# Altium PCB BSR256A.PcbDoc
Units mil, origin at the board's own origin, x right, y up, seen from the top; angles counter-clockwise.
Board outline 2710.5 x 1796.5 mil, 4 copper layers (Top Layer, Signal Layer 1, Signal Layer 2, Bottom Layer), stack 60.434 mil thick; 42 components, 12 nets, 58 pads, 44 vias.
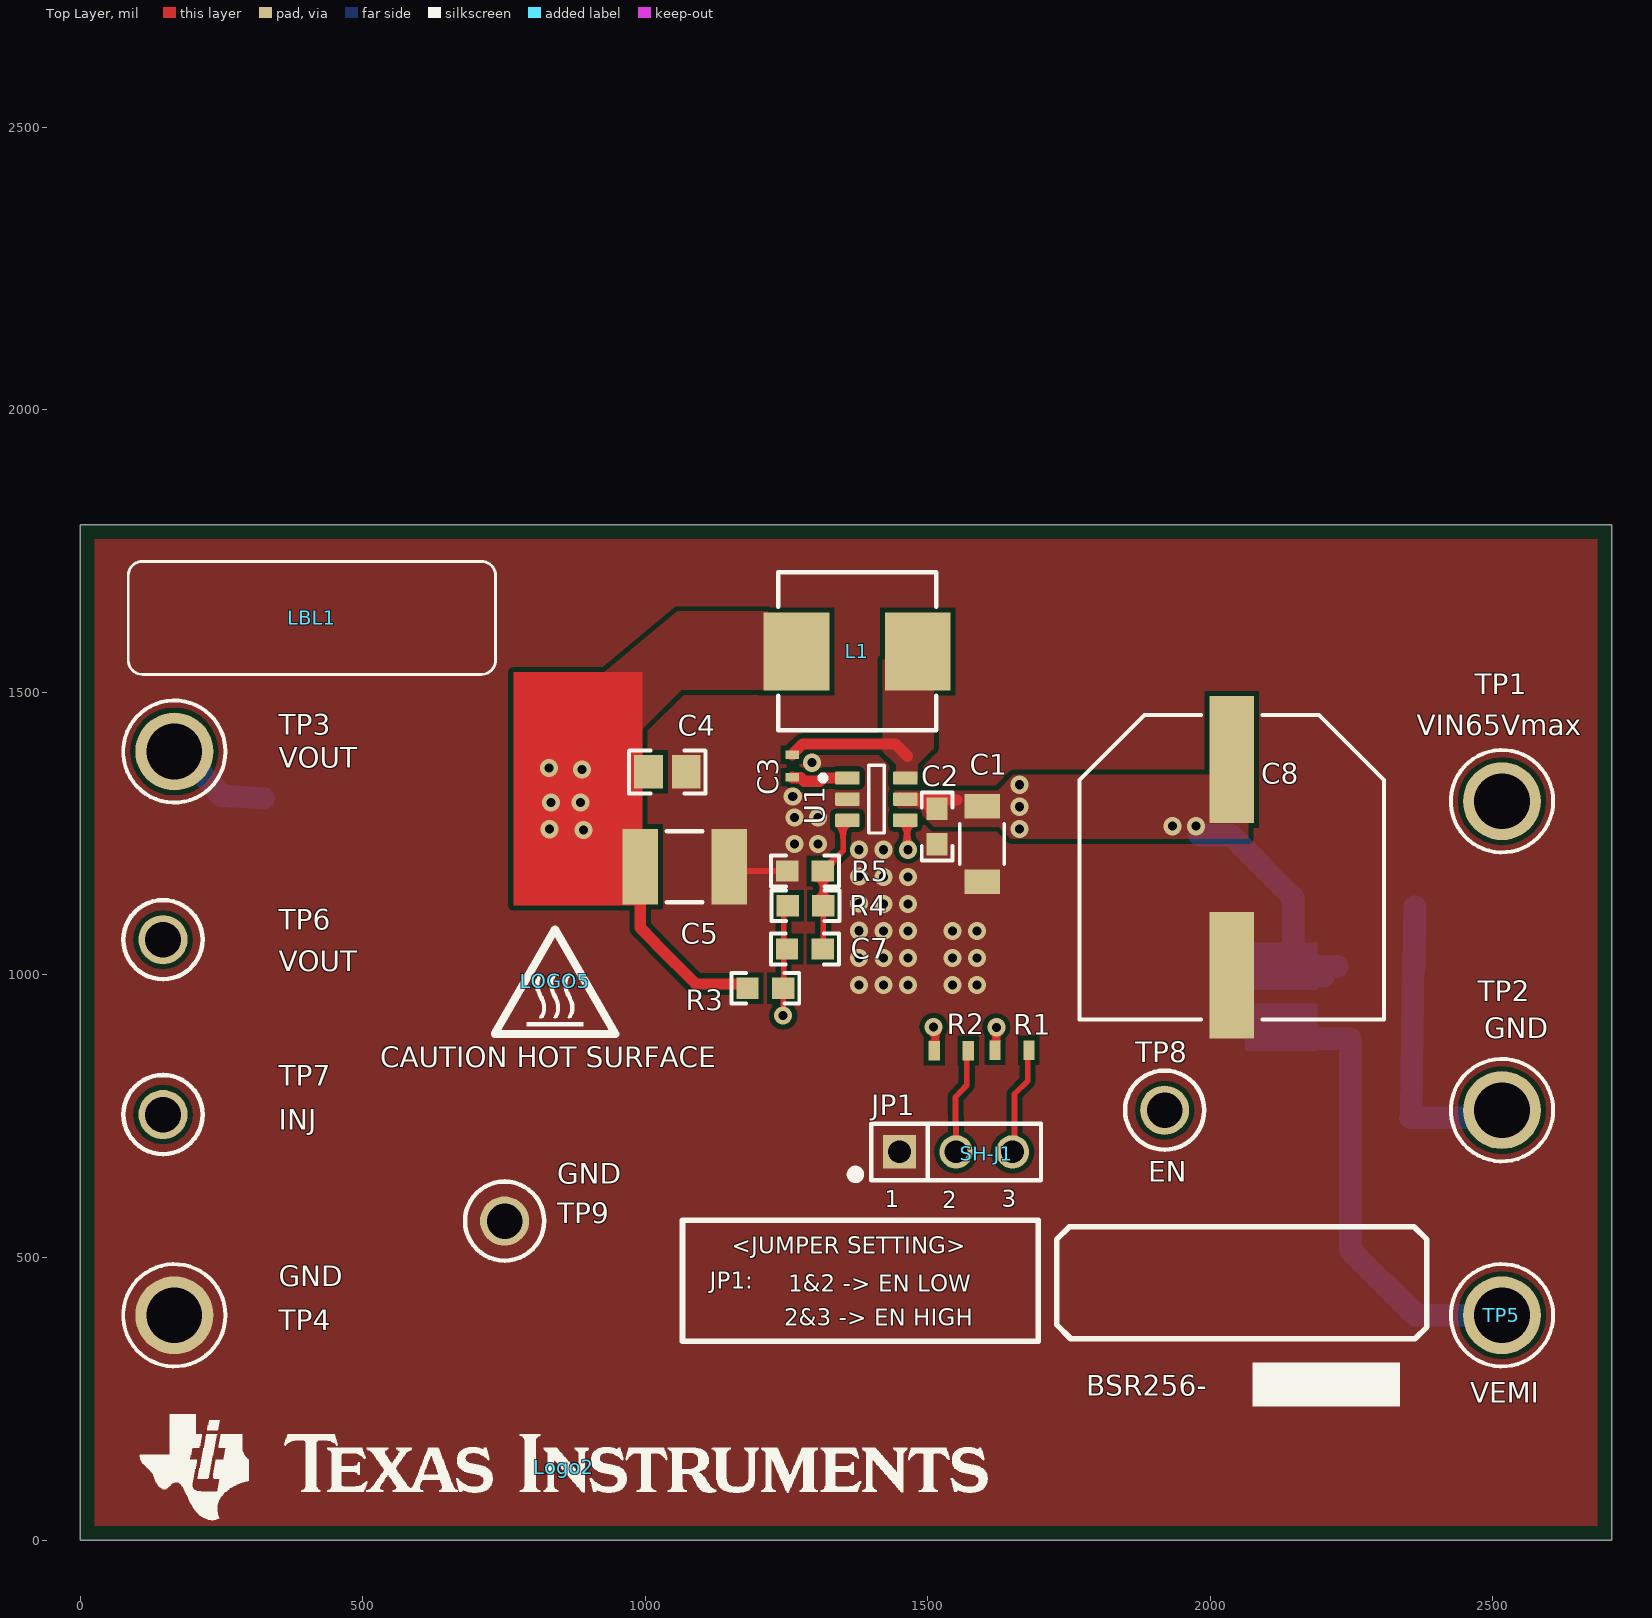
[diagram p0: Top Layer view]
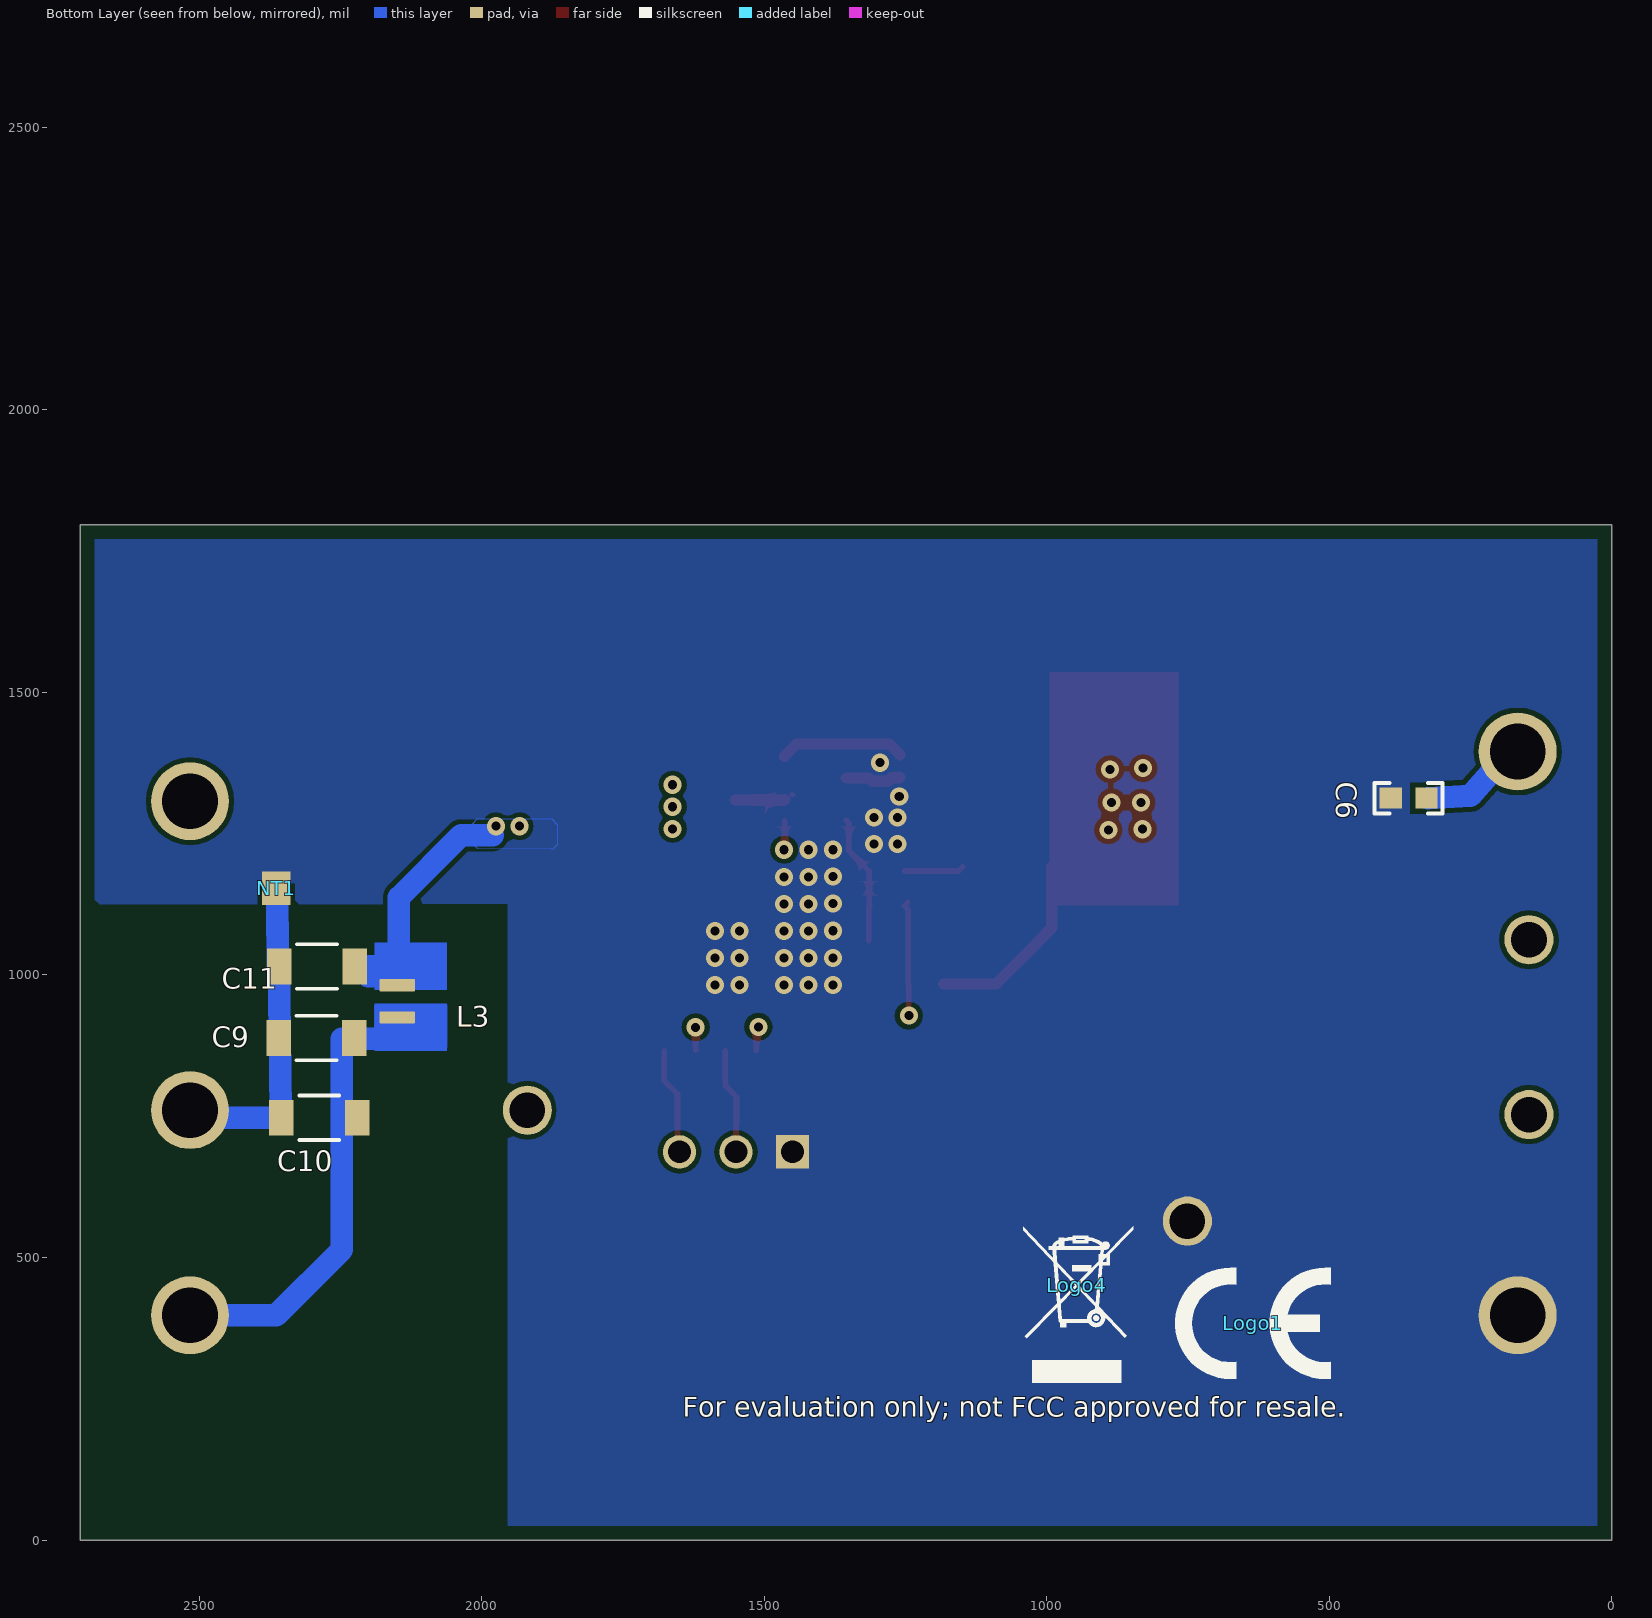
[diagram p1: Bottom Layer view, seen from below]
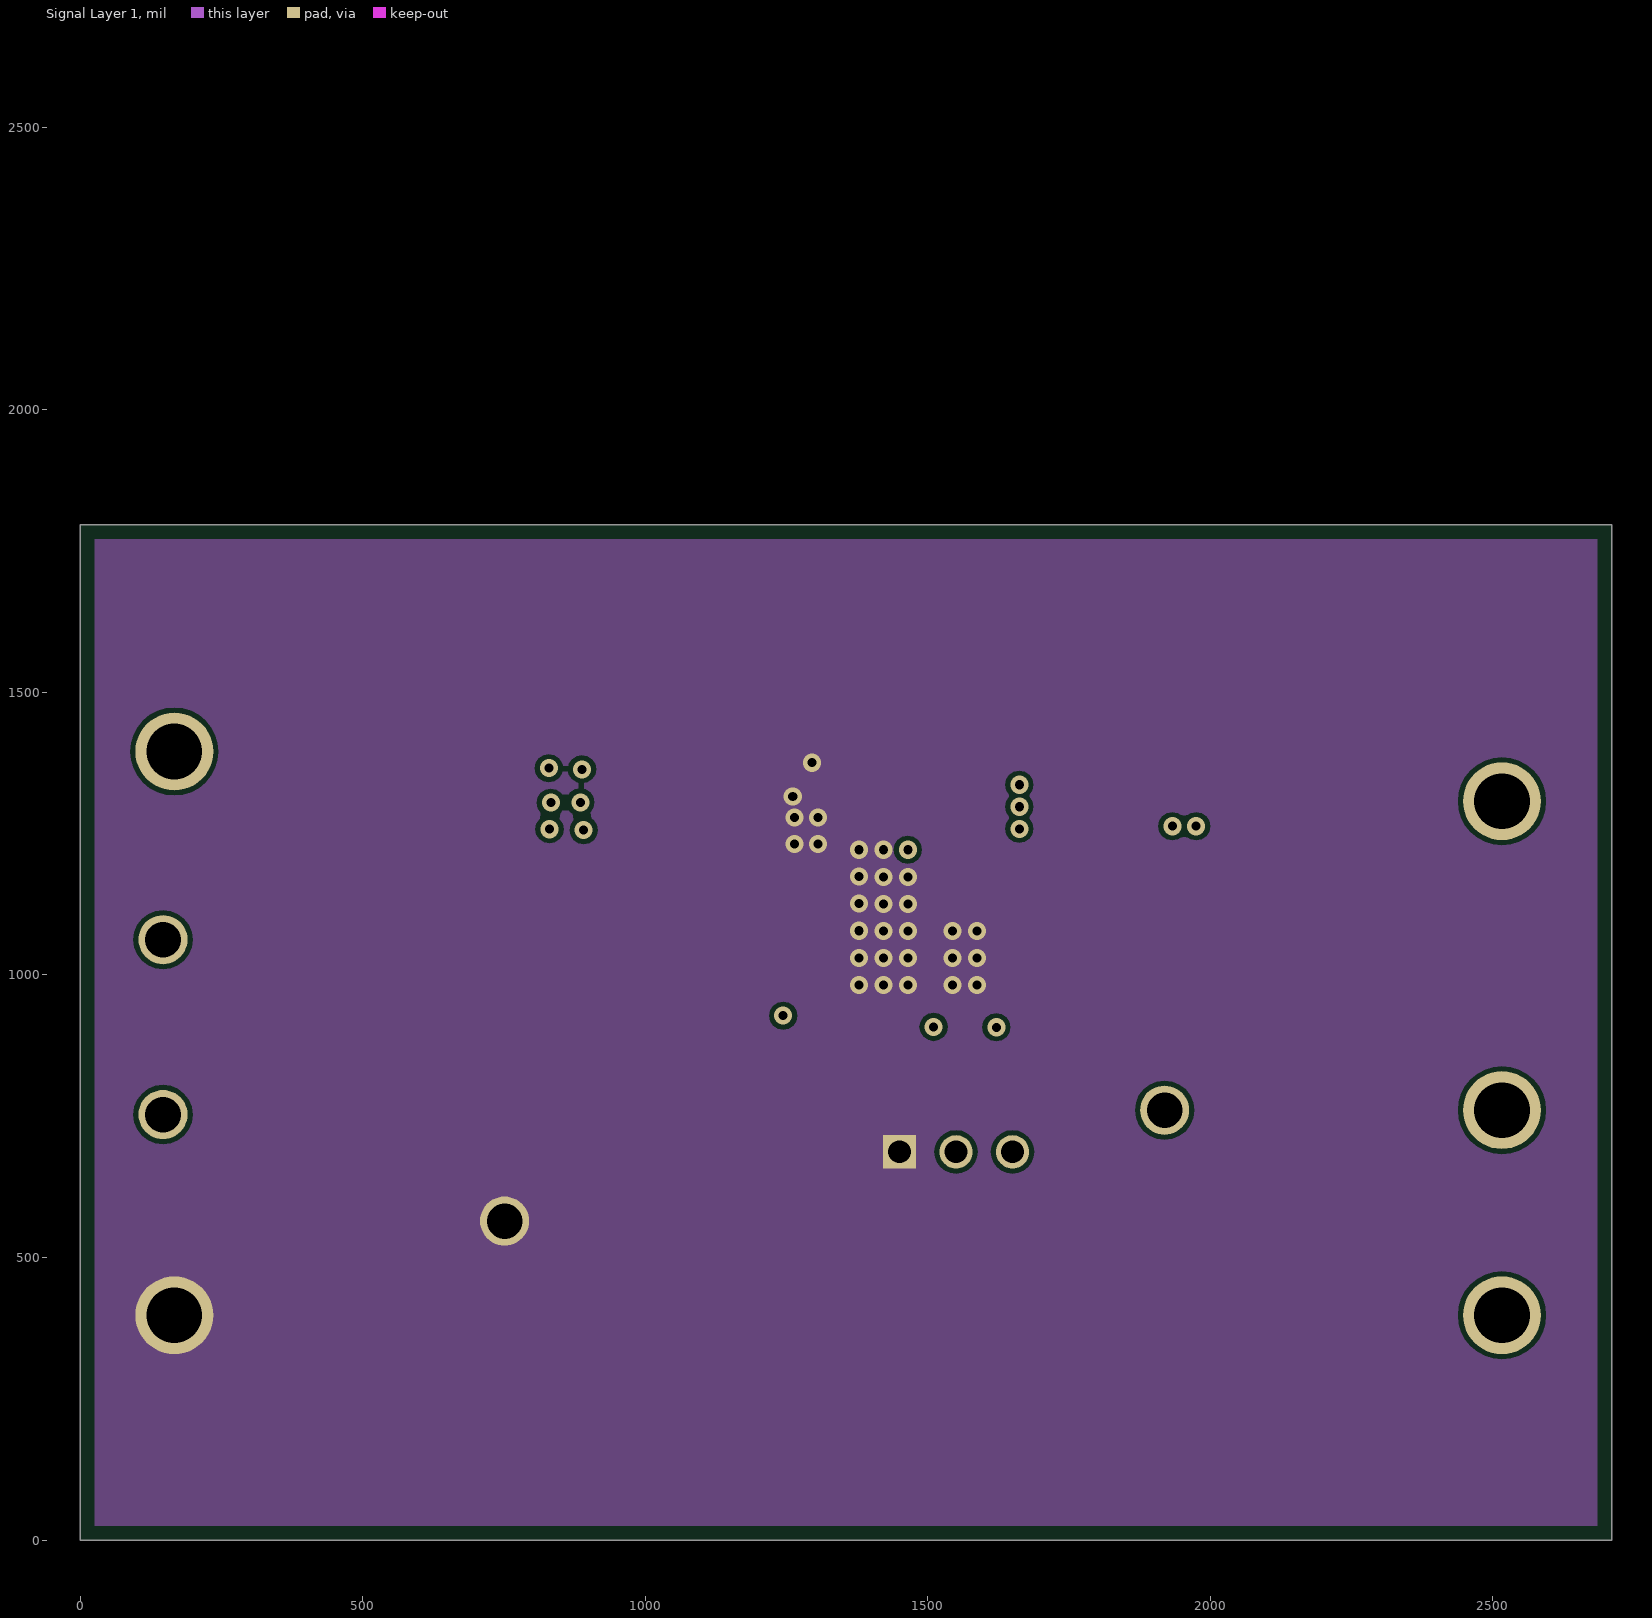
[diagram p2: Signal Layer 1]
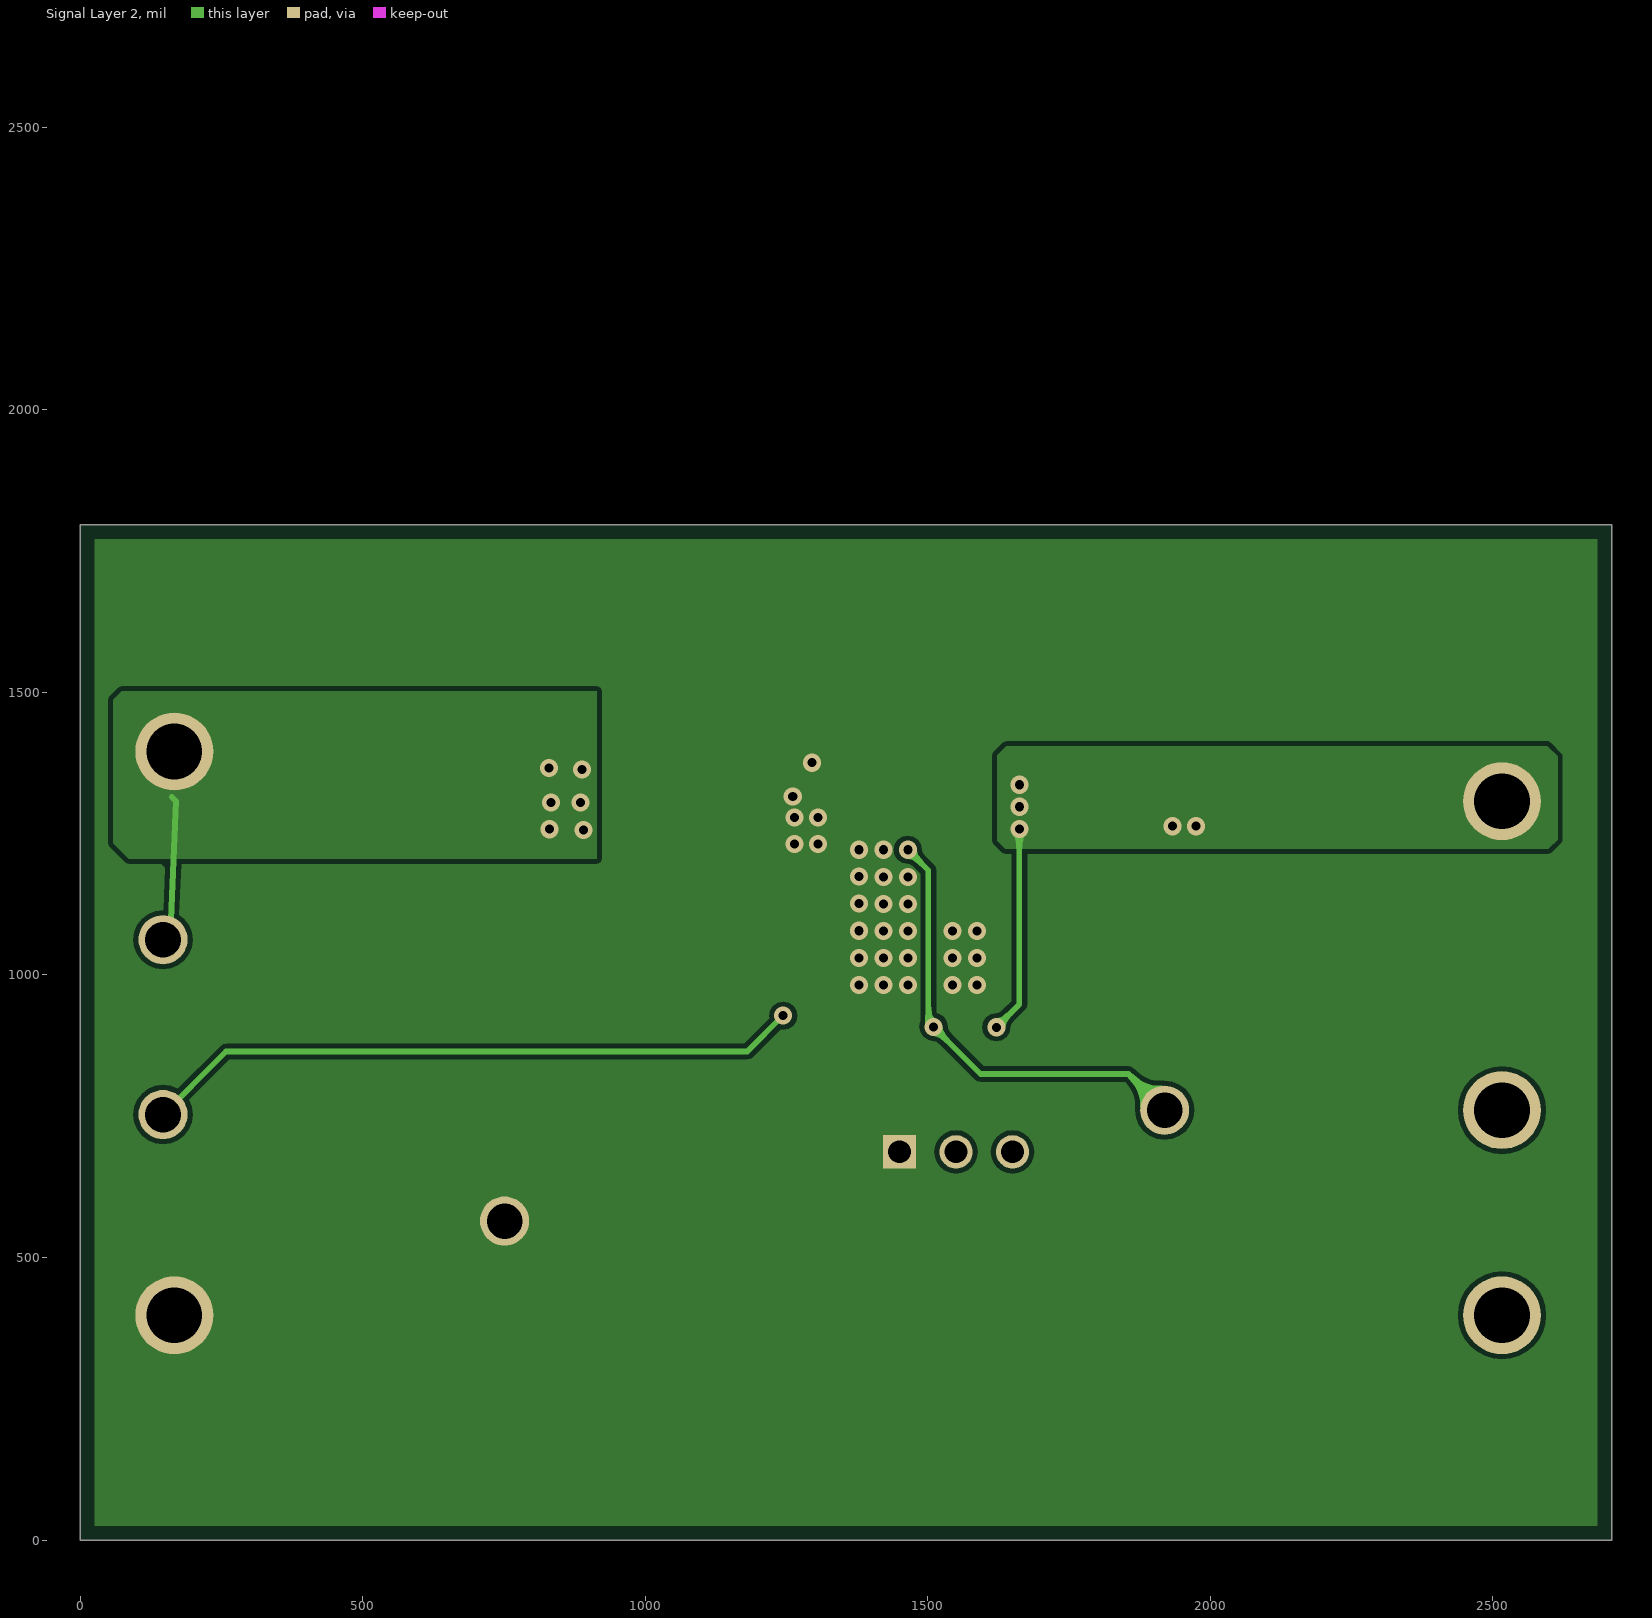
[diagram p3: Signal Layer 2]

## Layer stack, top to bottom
Top Solder: solder mask 0.4, Solder Resist, Dk 3.5
Top Layer: signal copper 2.8
Dielectric1: core 10, FR-4 High Tg, Dk 4.8
Signal Layer 1: signal copper 1.417
Dielectric 2: dielectric 32, FR-4 High Tg, Dk 4.2
Signal Layer 2: signal copper 1.417
Dielectric 3: dielectric 10, FR-4 High Tg, Dk 4.2
Bottom Layer: signal copper 2.8
Bottom Solder: solder mask 0.4, Solder Resist, Dk 3.5

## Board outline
0,0 0,1796.5 2710.5,1796.5 2710.5,0

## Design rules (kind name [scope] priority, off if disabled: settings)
AcuteAngle [All] p1: minimum=4.50000000000000E+0001 checktracksonly=FALSE
AssemblyTestPointUsage [All] p1: valid=2
BoardOutlineClearance BoardOutlineClearance_MountingHoles [OnCopper and InComponentClass('Mounting Holes')] p1: gap=40 ignorepadtopadclearanceinfootprint=FALSE
BoardOutlineClearance BoardOutlineClearance_Poly [OnCopper and IsPoly] p2: gap=25 ignorepadtopadclearanceinfootprint=FALSE
BoardOutlineClearance [OnCopper and Not InComponentClass('Logo') and not InComponentClass('FiducialMark') and not InRegion(1000,500,4000,800) and not InPoly] p3: gap=75 ignorepadtopadclearanceinfootprint=FALSE
Clearance Clearance_Keepouts [((IsTrack Or IsArc) And Not InPoly) And IsFree and IsKeepOut vs ((IsTrack Or IsArc) And Not InPoly) And IsFree and IsKeepOut] p1: gap=7 ignorepadtopadclearanceinfootprint=FALSE
Clearance Clearance_Poly [InPolygon] p2: gap=8.5 ignorepadtopadclearanceinfootprint=FALSE except(0: Arc-Hole Track-Hole SMDPad-Hole THPad-Hole Via-Hole Fill-Hole Poly-Hole Region-Hole Text-Hole)
Clearance [All] p3: gap=7 ignorepadtopadclearanceinfootprint=FALSE except(0: Arc-Arc Arc-Track Arc-SMDPad Arc-THPad Arc-Via Arc-Fill Arc-Poly Arc-Region Arc-Text Arc-Hole)
ComponentClearance ComponentClearance_MountingHoles_FiducialMarks [InComponentClass('Mounting Holes') vs InComponentClass('FiducialMark')] p1: gap=50 collisioncheckmode=3 verticalgap=10 showdistances=FALSE
ComponentClearance ComponentClearance_Shunt [InComponentClass('Header') vs InComponentClass('Shunt')] p2: gap=0 collisioncheckmode=3 verticalgap=0 showdistances=FALSE
ComponentClearance ComponentClearance_Logo [InComponentClass('Logo')] p3: gap=50 collisioncheckmode=3 verticalgap=10 showdistances=FALSE
ComponentClearance ComponentClearance_ScrewToNut [(HasFootprint('NY PMS 440 0025 PH')) vs (HasFootprint('Keystone_1902C'))] p4: gap=5 collisioncheckmode=3 verticalgap=10 showdistances=FALSE
ComponentClearance ComponentClearance_MountingHoles [InComponentClass('Mounting Holes')] p5: gap=250 collisioncheckmode=3 verticalgap=100000 showdistances=FALSE
ComponentClearance ComponentClearance_SmallPassives [HasFootprint('0201*') or HasFootprint('0402*') or HasFootprint('0508') or HasFootprint('0603*') or HasFootprint('0612') or HasFootprint('0805*') or HasFootprint('0815*') or HasFootprint('0830*') or HasFootprint('1206*') or HasFootprint('1210*') or HasFootprint('1808*') or HasFootprint('1812*') or HasFootprint('1825*') or HasFootprint('2010*') or HasFootprint('2220*') or HasFootprint('2225*') or HasFootprint('2512*') or HasFootprint('2728*') or HasFootprint('3518*') vs HasFootprint('0201*') or HasFootprint('0402*') or HasFootprint('0508') or HasFootprint('0603*') or HasFootprint('0612') or HasFootprint('0805*') or HasFootprint('0815*') or HasFootprint('0830*') or HasFootprint('1206*') or HasFootprint('1210*') or HasFootprint('1808*') or HasFootprint('1812*') or HasFootprint('1825*') or HasFootprint('2010*') or HasFootprint('2220*') or HasFootprint('2225*') or HasFootprint('2512*') or HasFootprint('2728*') or HasFootprint('3518*')] p6: gap=14.96 collisioncheckmode=3 verticalgap=10 showdistances=FALSE
ComponentClearance ComponentClearance_THtoSMT [IsThruComponent vs IsSMTComponent] p7: gap=10 collisioncheckmode=3 verticalgap=30 showdistances=FALSE
ComponentClearance ComponentClearance_THtoTH [IsThruComponent vs IsThruComponent] p8: gap=30 collisioncheckmode=3 verticalgap=30 showdistances=FALSE
ComponentClearance [All] p9: gap=30 collisioncheckmode=3 verticalgap=10 showdistances=FALSE
DiffPairsRouting [All] p1: maxlimit=100 minlimit=10 mostfreqgap=10 toplayer_minwidth=15 toplayer_maxwidth=15 toplayer_prefwidth=15 midlayer1_minwidth=15 midlayer1_maxwidth=15 midlayer1_prefwidth=15 midlayer2_minwidth=15 midlayer2_maxwidth=15 midlayer2_prefwidth=15 bottomlayer_minwidth=15 bottomlayer_maxwidth=15 bottomlayer_prefwidth=15 maxuncoupledlength=1000
FabricationTestPointUsage TestPointUsage [All] p1: valid=2 allowmultiple=FALSE
FabricationTestpoint Testpoint [All] p1: side=3 testpointundercomponent=TRUE minsize=40 maxsize=100 preferedsize=60 minholesize=0 maxholesize=40 preferedholesize=32 testpointgrid=1 allowsidetop=TRUE allowsidebottom=TRUE usegrid=TRUE gridtolerance=0.01
FanoutControl Fanout_LCC [IsLCC] p1: bgadir=Out bgaviamode=Centered fanoutstyle=Auto fanoutdirection=Alternating viagrid=1 // Fanout_LCC (Default Rule)
FanoutControl Fanout_BGA [IsBGA] p2: bgadir=Out bgaviamode=Centered fanoutstyle=Auto fanoutdirection=Alternating viagrid=1 // Fanout_BGA (Default Rule)
FanoutControl Fanout_Default [All] p4: bgadir=Out bgaviamode=Centered fanoutstyle=Auto fanoutdirection=Alternating viagrid=1 // Fanout_Default (Default Rule)
FanoutControl Fanout_Small [(CompPinCount < 5)] p5: bgadir=Out bgaviamode=Centered fanoutstyle=Auto fanoutdirection=OutThenIn viagrid=1 // Fanout_Small (Default Rule)
HoleSize [All] p1: absolutevalues=TRUE maxlimit=251 minlimit=7.87 maxpercent=80.000 minpercent=20.000
MinimumAnnularRing MinimumAnnularRing_ThermalPadVias [IsVia and InAnyComponent] p1: minimumring=5.91
MinimumAnnularRing [All] p2: minimumring=8
MinimumSolderMaskSliver MinimumSolderMaskSliver_Logo [InComponentClass('Logo') vs InComponentClass('Logo')] p1: minsoldermaskwidth=0.7
MinimumSolderMaskSliver [All] p2: minsoldermaskwidth=3.94
PlaneClearance [All] p1: clearance=0
PlaneConnect [All] p1: planeconnectstyle=Direct reliefexpansion=10 reliefentries=2 reliefconductorwidth=10 reliefairgap=10
PolygonConnect [All] p1: connectstyle=Direct reliefconductorwidth=10 reliefentries=4 polygonreliefangle="90 Angle" airgapwidth=10
RoutingVias ThermalPadVias [IsVia and InAnyComponent] p1: holewidth=7.87 width=19.68 viastyle="Through Hole" minholewidth=7.87 minwidth=19.68 maxholewidth=12.99 maxwidth=23.62
RoutingVias [All] p2: holewidth=16 width=34 viastyle="Through Hole" minholewidth=7.87 minwidth=26 maxholewidth=40 maxwidth=65
SilkToBoardRegionClearance [Not ((IsComment or IsDesignator) And (Hide <> 'False')) and not InRegion(1000,500,4000,800)] p1:
SilkToSilkClearance SilkToSilkClearance_Pb-FreeLogo [(HasFootprint('Pb-Free_Overlay_Medium') OR HasFootprint('Pb-Free_Overlay_Small')) vs (HasFootprint('Pb-Free_Overlay_Medium') OR HasFootprint('Pb-Free_Overlay_Small'))] p1: silktosilkclearance=0
SilkToSilkClearance [All] p2: silktosilkclearance=4
SilkToSolderMaskClearance SilkToComponentPadClearance [(IsPad or IsFill or IsRegion) and InAnycomponent] p1: minsilkscreentomaskgap=2 clearancetoexposedcopper=TRUE
SilkToSolderMaskClearance "Silk to Solder Mask Opening" [All] p2: minsilkscreentomaskgap=0.5 clearancetoexposedcopper=TRUE
SolderMaskExpansion [All] p1: expansion=1.85
Width [All] p1: maxlimit=100 minlimit=3 preferedwidth=10 midlayer1_minwidth=6 midlayer2_minwidth=6 bottomlayer_minwidth=6 minimp=50.000000 maximp=50.000000 favimp=50.000000 checkconnectedcopper=TRUE
14 further rules are at their usual default settings.

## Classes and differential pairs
component class BSR256A: C1 C2 C3 C4 C5 C6 C7 C8 C9 C10 C11 JP1 L1 L3 NT1 R1 R2 R3 R4 R5 TP1 TP2 TP3 TP4 TP5 TP6 TP7 TP8 TP9 U1
component class Label: LBL1
component class Shunt: SH-J1
component class BSR256A_Hardware: LBL1 Logo1 Logo2 Logo3 Logo4 LOGO5 LOGO7 SH-J1 ZZ1 ZZ2 ZZ3 ZZ4 ZZ5
component class Logo: Logo2
component class Header: JP1
component class AssemblyNote: ZZ1 ZZ2 ZZ3 ZZ4 ZZ5

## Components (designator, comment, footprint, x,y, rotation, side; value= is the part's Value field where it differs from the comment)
C1 "C3216X7S2A225K160AB" 1206_180 1596.07,1231.79 r270 top value=2.2uF
C2 "GRM188R72A104KA35J" 0603 1516.52,1262.74 r270 top value=0.1uF
C3 "GRM155R71E104KE14D" 0402S 1259.92,1369.77 r270 top value=0.1uF
C4 "GRM21BZ71E106KE15L" 0805 1039.04,1359.5 r0 top value=10uF
C5 "CGA8P1X7R1E226M250KC" 1812_280 1069.74,1191.5 r0 top value=22uF
C6 "C1608X7R1H104K080AA" 0603 359.5,1313 r0 bottom value=0.1uF
C7 "CGA3E2C0G1H220J080AA" 0603 1282.5,1046 r0 top value=22pF
C8 "EEV-TG2A470Q" Panasonic_H13 2038,1190.54 r270 top value=47uF
C9 "C3216X7S2A225K160AB" 1206_180 2292.5,888.5 r0 bottom value=2.2uF
C10 "C3216X7S2A225K160AB" 1206_180 2287.5,747.24 r0 bottom value=2.2uF
C11 "C3216X7S2A225K160AB" 1206_180 2291.57,1015 r0 bottom value=2.2uF
JP1 "PEC03SAAN" CONN_PEC03SAAN 1550.02,687 r0 top
L1 "74437349150" WE-LHMI_7050 1375,1572.83 r180 top value=15uH
L3 "DFE201612E-1R0M=P2" DFE201612E 2149.5,953.24 r90 bottom value=1uH
LBL1 "THT-14-423-10" Label_650x200 410,1632 r0 top
Logo1 "CE Mark" CE_Mark_5mm 635,383.5 r180 bottom
Logo2 "Texas Instruments" TI_Horizontal_Overlay_Medium 855.5,128.74 r0 top
Logo3 "FCC disclaimer" FCC_disclaimer -358.76,747 r90 bottom
Logo4 "WEEE logo" WEEE_Minimum 946.5,450.96 r180 bottom
LOGO5 "CAUTION HOT SURFACE" IEC_HotSurface_Small 840.5,988.5 r0 top
NT1 "Net-Tie" Net-Tie_50milWide_30milLong 2363.5,1153.5 r90 bottom net-tie
R1 "CRCW0603402KFKEA" 0603S 1649.02,866.74 r180 top value=402k
R2 "CRCW0603133KFKEA" 0603S 1541.44,866.04 r0 top value=133k
R3 "Resistor" 0603 1212.5,976.5 r0 top value=49.9
R4 "RT0603DRE0769K8L" 0603 1283.5,1122.54 r180 top value=69.8k
R5 "RC0603FR-0722K1L" 0603 1282.81,1184.07 r0 top value=22.1k
SH-J1 "SNT-100-BK-G" SNT-100-BK-G 1604.5,684 r180 top value=1x2
TP1 "1502-2" Keystone1502-2 2516.24,1307.54 r0 top
TP2 "1502-2" Keystone1502-2 2516.24,760.8 r0 top
TP3 "1502-2" Keystone1502-2 166.5,1395.5 r0 top
TP4 "1502-2" Keystone1502-2 166.5,397.74 r0 top
TP5 "1502-2" Keystone1502-2 2516.24,397.74 r0 top
TP6 "5010" Keystone5010 146.44,1062.5 r0 top
TP7 "5014" Keystone5014 146.44,753 r0 top
TP8 "5014" Keystone5014 1919.24,760.74 r0 top
TP9 "5011" Keystone5011 751,564.5 r0 top
U1 "LMR51610DBVR" DBV0006A-MFG 1409.02,1311.24 r0 top
ZZ1 "This Assembly Note is for PCB labels only" AssemblyNoteLabel 197,3292.5 r0 top
ZZ2 "These assemblies are ESD sensitive, ESD precautions shall be observed." AssemblyNote 197,3169.5 r0 top
ZZ3 "These assemblies must be clean and free from flux and all contaminants. Use of no clean flux is not acceptable." AssemblyNote 197,3046 r0 top
ZZ4 "These assemblies must comply with workmanship standards IPC-A-610 Class 2, unless otherwise specified." AssemblyNote 197,2913.5 r0 top
ZZ5 "SH-J1 should be put in the 2 & 3 pin of JP1 by default." AssemblyNote 197,2800.5 r0 top

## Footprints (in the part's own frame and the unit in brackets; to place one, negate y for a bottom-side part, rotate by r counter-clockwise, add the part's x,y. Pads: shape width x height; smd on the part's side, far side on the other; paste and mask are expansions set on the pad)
0402S [mil] "Based on C0402S footprint from PADS legacy"
  rect 15x24 smd: 1(-20,0) 2(20,0)
  body extent -22,-12 22,12, height 24
0603 [mm] "0603 from SM-752 data"
  rect 1x0.95 smd: 1(-0.8,0) 2(0.8,0)
  silkscreen extent -1.52,-0.69 1.52,0.69, body extent -0.87,-0.47 0.87,0.47, height 1
0603S [mil]
  rect 20x35 smd: 1(-30,0) 2(30,0)
  body extent -34,-19 34,19, height 39
0805 [mm] "0805 from SM-752 data"
  rect 1.3x1.5 smd: 1(-0.85,0) 2(0.85,0)
  silkscreen extent -1.72,-0.97 1.72,0.97, body extent -1.1,-0.72 1.1,0.72, height 1.45
1206_180 [mm] "1206_180"
  rect 1.1x1.6 smd: 1(-1.7,0) 2(1.7,0)
  silkscreen extent -0.9,-1 0.9,1, body extent -1.75,-0.95 1.75,0.95, height 1.8
1812_280 [mm] "1812"
  rect 1.6x3.4 smd: 1(-2,0) 2(2,0)
  silkscreen extent -0.8,-1.6 0.8,1.6, body extent -2.4,-1.7 2.4,1.7, height 2.8
AssemblyNote [mil] "Assembly Note"
AssemblyNoteLabel [mil] "Assembly Note for PCB Labels"
CE_Mark_5mm [mil] "Minimum text height for CE Mark"
  silkscreen extent -138,-98 138,98
CONN_PEC03SAAN [mm] "SULLINS"
  rect 1.5x1.5 hole 1.016: 1(-2.54,0)
  round 1.5 hole 1.016: 2(0,0) 3(2.54,0)
  silkscreen extent -4.72,-1.27 3.81,1.27, body extent -3.84,-1.3 3.84,1.3, height 8.38
DBV0006A-MFG [mm]
  rrect17% 1.1x0.6 smd paste+0 mask+0: 1(-1.3,0.95) 2(-1.3,0) 3(-1.3,-0.95) 4(1.3,-0.95) 5(1.3,0) 6(1.3,0.95)
  silkscreen extent -2.52,-1.53 0.35,1.53, body extent -1.95,-1.78 1.95,1.78, height 0.25
DFE201612E [mm] "MuRata recommended"
  rrect18% 0.55x1.6 smd: 1(-0.725,0) 2(0.725,0)
  body extent -1.1,-0.9 1.1,0.9, height 1.2
FCC_disclaimer [mil]
IEC_HotSurface_Small [mil]
  silkscreen extent -107,-93 107,92
Keystone1502-2 [mm] "Double Turret"
  round 3.5 hole 2.5: 1(0,0)
  silkscreen extent -2.3,-2.3 2.3,2.3, body extent -1.6,-1.6 1.59,1.6, height 5.62
Keystone5010 [mil] "Keystone Multipurpose loops"
  round 87 hole 63: 1(0,0)
  silkscreen extent -70,-70 70,70, body extent -63,-63 63,62, height 319
Keystone5011 [mil] "Keystone Multipurpose loops"
  round 87 hole 63: 1(0,0)
  silkscreen extent -70,-70 70,70, body extent -63,-63 63,62, height 319
Keystone5014 [mil] "Keystone Multipurpose loops"
  round 87 hole 63: 1(0,0)
  silkscreen extent -70,-70 70,70, body extent -63,-63 63,62, height 319
Label_650x200 [mil] "Thermal Transfer Label"
  round 1 on Mech13: 0(0,0)
  silkscreen extent -325,-100 325,100, body extent -325,-100 325,100, height 1
Net-Tie_50milWide_30milLong [mil] "50mil net tie, no solder mask opening, no solder paste"
  rect 30x50 smd paste-20 mask-20: 1(-15,0) 2(15,0)
Panasonic_H13 [mm] "12.5 x 13.5mm:  Panasonic H13"
  rect 5.7x2 smd: 1(-4.85,0) 2(4.85,0)
  silkscreen extent -6.85,-6.85 6.85,6.85, body extent -6.9,-6.75 6.9,6.75, height 13.5
SNT-100-BK-G [mil] "Samtec STEP model"
  round 1 on Mech3: 0(0,0)
  body extent -100,-50 100,50, height 344
TI_Horizontal_Overlay_Medium [mil]
  silkscreen extent -750,-94 750,94
WE-LHMI_7050 [mm] "Wurth"
  rect 2.95x3.5 smd: 1(-2.725,0) 2(2.725,0)
  silkscreen extent -3.55,-3.55 3.55,3.55, body extent -3.8,-3.45 3.8,3.45, height 5
WEEE_Minimum [mil] "WEEElie bin"
  silkscreen extent -95,-172 99,104

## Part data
C1 C9 C10 C11: library part CMP-0008724-2, "CAP, CERM, 2.2 uF, 100 V, +/- 10%, X7S, 1206", Cap_Case=1206_180, Manufacturer=TDK, Supplier Part Number 1=445-5207-1-ND, TempCo=X7S, Tolerance_%=10%, Value1="0.005718 ohm", Value2=100V, ValueDisplayed=2.2uF
C2: library part CMP-0007470-5, "CAP, CERM, 0.1 uF, 100 V, +/- 10%, X7R, 0603", Cap_Case=0603, Manufacturer=MuRata, Supplier Part Number 1=490-6439-1-ND, TempCo=X7R, Tolerance_%=10%, Value1=Unknown, Value2=100V, ValueDisplayed=0.1uF
C3: library part CMP-0006659-1, "CAP, CERM, 0.1 uF, 25 V, +/- 10%, X7R, 0402", Cap_Case=0402, Manufacturer=MuRata, Supplier Part Number 1=490-10698-1-ND, TempCo=X7R, Tolerance_%=10%, Value1=Unknown, Value2=25V, ValueDisplayed=0.1uF
C4: library part CMP-0008378-2, "CAP, CERM, 10 uF, 25 V, +/- 10%, X7R, 0805", Cap_Case=0805, Manufacturer=MuRata, Supplier Part Number 1=81-GRM21BZ71E106KE5L, TempCo=X7R, Tolerance_%=10%, Value1=Unknown, Value2=25V, ValueDisplayed=10uF
C5: library part CMP-0009402-2, "CAP, CERM, 22 uF, 25 V, +/- 20%, X7R, AEC-Q200 Grade 1,", Cap_Case=1812_280, Manufacturer=TDK, Supplier Part Number 1=445-7910-1-ND, TempCo=X7R, Tolerance_%=20%, Value1="0.002434 ohm", Value2=25V, ValueDisplayed=22uF
C6: library part CMP-0007044-3, "CAP, CERM, 0.1 uF, 50 V, +/- 10%, X7R, 0603", Cap_Case=0603, Manufacturer=TDK, Supplier Part Number 1=445-1314-1-ND, TempCo=X7R, Tolerance_%=10%, Value1="0.0296 ohm", Value2=50V, ValueDisplayed=0.1uF
C7: library part CMP-0007071-3, "CAP, CERM, 22 pF, 50 V, +/- 5%, C0G/NP0, AEC-Q200 Grade 1, 0603", Cap_Case=0603, Manufacturer=TDK, Supplier Part Number 1=445-5632-1-ND, TempCo=C0G/NP0, Tolerance_%=5%, Value1=Unknown, Value2=50V, ValueDisplayed=22pF
C8: library part CMP-0011227-2, "CAP, AL, 47 uF, 100 V, +/- 20%, 0.42 ohm, AEC-Q200 Grade 1, SMD", Cap_Case=12.5x13.5mm, Manufacturer=Panasonic, Supplier Part Number 1=PCE3701CT-ND, Tolerance_%=20%, Value1="0.42 ohm", Value2=100V, ValueDisplayed=47uF
JP1: library part CMP-0002338-1, "Header, 100mil, 3x1, Tin, TH", Color=Black, Current_A=3A, Manufacturer="Sullins Connector Solutions", Supplier Part Number 1=S1012E-03-ND, Voltage_V=1.8kV
L1: library part CMP-0064491-2, "Inductor, Shielded Drum Core, Powdered Iron, 15 uH, 2.75 A, 0.092 ohm, SMD", Manufacturer="Wurth Elektronik", Supplier Part Number 1=710-74437349150, Value1="0.092 ohm", Value2=2.75A, ValueDisplayed=15uH
L3: library part CMP-0080773-1, "Inductor, Shielded, Metal Composite, 1 µH, 2.9 A, 0.048 ohm, SMD", Manufacturer=MuRata, PartNumber=DFE201612E-1R0M{}P2, Value1="0.048 ohm", Value2=2.9A, ValueDisplayed=1µH
LBL1: library part CMP-0003625-1, "Thermal Transfer Printable Labels, 0.650\" W x 0.200\" H - 10,000 per roll", Manufacturer=Brady, Supplier Part Number 1=97C5133
Logo1: library part CMP-0074844-1
Logo2: library part CMP-0074838-1, "Texas Instrument Corporate Signature"
Logo3: library part CMP-0074847-1, "FCC_disclaimer"
Logo4: library part CMP-0074769-1
LOGO5: library part CMP-0074837-1, "IEC 61010-1 Hot Surface Warning"
NT1: library part CMP-0078142-2, "Single point connection between nets.", Manufacturer=N/A
R1: library part CMP-0022408-4, "RES, 402 k, 1%, 0.1 W, AEC-Q200 Grade 0, 0603", Manufacturer=Vishay-Dale, Power_W=100mW, Supplier Part Number 1=541-402KHCT-ND, TempCo="100 ppm/C", Tolerance_%=1%, Value2=0.1W, Value_Code=402k
R2: library part CMP-0022038-4, "RES, 133 k, 1%, 0.1 W, AEC-Q200 Grade 0, 0603", Manufacturer=Vishay-Dale, Power_W=100mW, Supplier Part Number 1=541-133KHCT-ND, TempCo="100 ppm/C", Tolerance_%=1%, Value2=0.1W, Value_Code=133k
R3: library part CMP-0022448-3, "RES, 49.9, 1%, 0.1 W, 0603", Manufacturer=Vishay-Dale, PartNumber=CRCW060349R9FKEA, Power_W=100mW, Supplier Part Number 1=541-49.9HCT-ND, TempCo="100 ppm/C", Tolerance_%=1%, Value2=0.1W, Value_Code=49R9, ValueDisplayed=49.9
R4: library part CMP-0025509-2, "RES, 69.8 k, 0.5%, 0.1 W, 0603", Manufacturer="Yageo America", Power_W=100mW, TempCo="50 ppm/C", Tolerance_%=0.5%, Value2=0.1W, Value_Code=69k8, ValueDisplayed=69.8k
R5: library part CMP-0022923-5, "RES, 22.1 k, 1%, 0.1 W, 0603", Manufacturer=Yageo, Power_W=100mW, Supplier Part Number 1=311-22.1KHRCT-ND, TempCo="100 ppm/C", Tolerance_%=1%, Value2=0.1W, Value_Code=22k1, ValueDisplayed=22.1k
SH-J1: library part CMP-0003623-3, "Shunt, 100mil, Gold plated, Black", Alternate Manufacturer=3M, Alternate PartNumber=969102-0000-DA, Manufacturer=Samtec, Supplier Part Number 1=SAM8858-ND
TP1 TP2 TP3 TP4 TP5: library part CMP-0055113-1, "Terminal, Turret, TH, Double", Manufacturer=Keystone, Supplier Part Number 1=36-1502-2-ND
TP6: library part CMP-0055147-1, "Test Point, Multipurpose, Red, TH", Color=Red, Manufacturer=Keystone, Supplier Part Number 1=36-5010-ND
TP7 TP8: library part CMP-0055151-1, "Test Point, Multipurpose, Yellow, TH", Color=Yellow, Manufacturer=Keystone, Supplier Part Number 1=36-5014-ND
TP9: library part CMP-0055148-1, "Test Point, Multipurpose, Black, TH", Color=Black, Manufacturer=Keystone, Supplier Part Number 1=36-5011-ND
U1: library part CMP-0096066-1, "65V, 1A Synchronous Step-Down DC-DC Converter", Manufacturer="Texas Instruments", Max Supply Voltage=65V, Min Supply Voltage=4V, Nominal Supply Current=25-420uA, Operating Temperature Range="-40°C to +150°C", Output Voltage=0.8-28V, Switching Frequency=400/1100kHz
ZZ1: library part CMP-0003616-3
ZZ2: library part CMP-0077236-1
ZZ3: library part CMP-0077237-1
ZZ4: library part CMP-0077238-1
ZZ5: library part CMP-0077238-1, "These assemblies must comply with workmanship standards IPC-A-610 Class 2, unless otherwise specified."

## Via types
v1: diameter 32, hole 16, Top Layer to Bottom Layer, tented both sides, 44 vias

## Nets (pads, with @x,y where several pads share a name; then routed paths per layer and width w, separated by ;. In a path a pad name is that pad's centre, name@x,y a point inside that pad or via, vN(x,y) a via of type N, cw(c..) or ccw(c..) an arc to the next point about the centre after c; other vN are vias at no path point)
EN: R2.1 TP8.1 U1.4 | length 897.7
  Top Layer w10: U1.4@1463.4,1272.79 1463.4,1222.87 v1(1464.63,1221.64) ; v1(1510.25,908.04) 1513.88,904.4 R2.1@1513.88,866.04
  Signal Layer 2 w10: v1(1464.63,1221.64) 1501.13,1185.15 1501.13,917.16 v1(1510.25,908.04) 1593.55,824.74 1855.24,824.74 TP8.1
GND: C1.2 C2.2 C4.2 C5.2 C6.2 C8.2 JP1.1 NT1.2 R5.1 TP4.1 TP9.1 U1.2 | length 105.9
  Top Layer w10: C5.2 1155.91,1184.07 R5.1
  other v1: 1378.13,982.34 1421.38,982.34 1464.63,982.34 1543.88,982.34 1587.13,982.34 1378.13,1030.31 1421.38,1030.2 1464.63,1030.2 1543.88,1030.2 1587.13,1030.2 1378.13,1078.28 1421.38,1078.06 1464.63,1078.06 1543.88,1078.06 1587.13,1078.06 1378.13,1126.25 1421.38,1125.92 1464.63,1125.92 1378.13,1174.22 1421.38,1173.78 1464.63,1173.78 1378.13,1221.64 1421.38,1221.64 1263.83,1231.79 1305.33,1231.79 1263.83,1278.79 1305.33,1278.79 1261,1316 1294.92,1375.69
INJ: C7.1 R3.2 R4.2 TP7.1 | length 1388
  Top Layer w10: v1(1244,928) 1244,983 1245,984 1245,1115.53 R4.2 R4.2@1246.24,1128.3
  Signal Layer 2 w10: TP7.1@138,744.5 258,864.5 1180.5,864.5 v1(1244,928)
NetC3_2: C3.2 U1.1 | length 100.4
  Top Layer w20: C3.2 1260.69,1349 1274.94,1349 1281.25,1342.69 1308.59,1342.69 1314.54,1348.64 U1.1@1354.89,1348.64
NetC7_2: C7.2 R4.1 R5.2 U1.3 | length 224.1
  Top Layer w10: R4.1@1313.54,1122.54 1315,1121.08 C7.2@1315,1061 ; R4.1@1314.31,1128.68 R5.2 1350.13,1219.89 1350.13,1269.08 U1.3@1354.89,1273.84
NetC9_2: C9.2 C10.2 C11.2 NT1.1 TP2.1 | length 550.2
  Bottom Layer w40: C10.2 2502.69,747.24 TP2.1 ; C10.2@2356,759.24 C11.2@2359,1028.5 ; C11.2@2360.38,1007.47 2360.48,1014.97 2362,1121
NetJP1_2: JP1.2 R2.2 | length 187.1
  Top Layer w10: JP1.2 1549.09,784.11 1569,804.84 R2.2@1569,866.04
NetJP1_3: JP1.3 R1.1 | length 188.2
  Top Layer w10: JP1.3@1653.5,687.5 1653.5,789.34 1676.81,812.65 R1.1@1676.81,866.04
SW: C3.1 L1.1 U1.6 | length 221.1
  Top Layer w20: C3.1 1259.92,1390.27 1278.33,1408.69 1442.55,1408.69 1464,1387.24
VIN: C1.1 C2.1 C8.1 C11.1 L3.2 R1.2 TP1.1 U1.5 | length 958.7
  Top Layer w10: U1.5@1450.07,1318.79 U1.5@1450.24,1318.97 ; v1(1621.41,907.47) 1621.46,907.41 R1.2@1621.46,866.74
  Top Layer w20: U1.5@1463.4,1310.19 1463.81,1309.79 1551.13,1309.79
  Signal Layer 2 w10: v1(1621.41,907.47) 1662,948.06 v1(1662,1258.74) v1@1662,1259.74
  Bottom Layer w40: 1980.5,1247.24 2036.5,1247.24 2146.5,1137.24 2146.5,1012.74 2161,998.24 2201,998.24 2184.24,1015 C11.1
  other v1: 1932.82,1263.31 1974.94,1263.31 1662,1297.74 1662,1336.74
VIN_EMI_P: C9.1 C10.1 L3.1 TP5.1 | length 781
  Bottom Layer w40: 2155.76,887.5 2247.5,887.5 2247.5,513.8 2363.56,397.74 TP5.1@2515,397.74
VOUT: C4.1 C5.1 C6.1 L1.2 R3.1 TP3.1 TP6.1 | length 767.2
  Top Layer w20: C5.1 991,1083.5 1016.75,1057.75 ; 1019.5,1054 1089.5,984 R3.1@1182.01,984
  Signal Layer 2 w10: TP6.1@159.6,1076.67 169.5,1307.5 162,1315
  Bottom Layer w40: TP3.1@174,1403 174.41,1402.54 250.16,1317.38 C6.1@325.08,1313
  other v1: 891,1256.5 830.5,1258 833,1305 885,1305.5 888,1364 829.5,1366
pads on no net: LBL1.0 SH-J1.0

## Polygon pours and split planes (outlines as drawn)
GND on Top Layer "TOP_LAYER_GND_P096" (solid, remove dead copper, pour order 96): 23.5,1782 10.5,1769 10.5,21 2684.5,21 2689.5,26 2687,28.5 2687,1779.5 15.5,1779.5 13,1777
no net on Top Layer "TOP_LAYER_NONET_P094" (solid, remove dead copper, pour order 94): 910.5,1129
VOUT on Top Layer "TOP_LAYER_VOUT_P092" (solid, remove dead copper, pour order 92): 1215.5,1643.5 1056.5,1643.5 923,1532.25 923,1463.5 973,1413.5 1064.5,1505 1244,1505 1247.5,1508.5 1247.5,1613 1236.5,1624
VIN on Top Layer "TOP_LAYER_VIN_P010" (solid, remove dead copper, pour order 10): 1623.62,1326.29 1651.34,1354.24 2067.56,1354.24 2067.56,1241.01 1647.16,1241.01 1625.38,1262.8 1510.87,1262.8 1478.38,1295.29 1441.83,1295.29 1441.83,1326.29 1492.13,1326.29 1596.07,1326.29
SW on Top Layer "TOP_LAYER_SW_P016" (solid, remove dead copper, pour order 16): 1420,1395.38 1444.35,1371.79 1444.35,1340.79 1482.52,1340.79 1482.52,1372.93 1510.83,1401.24 1510.83,1540.52 1493.35,1558 1420,1558
GND on Signal Layer 2 "SIGNAL_LAYER_2_GND_P084" (solid, remove dead copper, pour order 84): -13.49,-5.32 2697.01,-5.32 2697.01,1791.18 -8.49,1791.18 -8.49,-0.32
VIN on Signal Layer 2 "SIGNAL_LAYER_2_VIN_P060" (solid, remove dead copper, pour order 60): 2030,1223.27 2224.3,1223.27 2233.02,1223.27 2598.05,1223.27 2614.52,1239.74 2614.52,1386.74 2596.02,1405.24 1860,1405.24 1639.24,1405.24 1623,1389 1623,1237.29 1637.02,1223.27 1868.52,1223.27 2027.52,1223.27
VOUT on Signal Layer 2 "SIGNAL_LAYER_2_VOUT_P050" (solid, remove dead copper, pour order 50): 914,1502.25 914,1205.75 85.76,1205.75 58.52,1232.99 58.52,1487.27 73.5,1502.25
GND on Bottom Layer "BOTTOM_LAYER_GND_P086" (solid, remove dead copper, pour order 86): 0.94,-9 4.44,-5.5 2710.94,-5.5 2710.94,1787 2711.44,1787.5 5.94,1787.5 5.94,-4
no net on Bottom Layer "BOTTOM_LAYER_NONET_P072" (solid, remove dead copper, pour order 72): 1877.64,1223.27 1872.96,1223.27 1865,1231.24 1865,1265.24 1875.5,1275.74 2008.5,1275.74 2018,1266.24 2018,1234.24 2007.93,1224.17
VIN_EMI_P on Bottom Layer "BOTTOM_LAYER_VIN_EMI_P_P078" (solid, remove dead copper, pour order 78): 2189.5,946.29 2061.5,946.29 2061.5,872.24 2189.5,872.24
GND on Signal Layer 1 "SIGNAL_LAYER_1_GND_P082" (solid, remove dead copper, pour order 82): 2728.03,-9.86 2728.03,1786.64 17.53,1786.64 17.53,-9.86

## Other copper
Top Layer:
  rectangle net VOUT: 766.5,1123 995,1536
Signal Layer 2:
  region net VOUT: 958,1169.5
Bottom Layer:
  rectangle net VIN: 2061,973.74 2189.5,1057.24
  rectangle net VIN_EMI_P: 2061,865.74 2189.5,949.24
  pour cut-out: 1954.25,1125.8 2681.87,1124.59 2680.25,-36.8 1954.25,-36.8

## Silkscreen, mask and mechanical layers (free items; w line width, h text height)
Top Overlay:
  rectangle: 2075,236.5 2336,314
  lines w10: 1066,352 1695.57,352 1695.57,566 1066,566 1066,352 ; 1728,381.37 1728,531.87 1750.52,554.39 2360.48,554.39 2383.32,531.55 2383.32,377.2 2362.38,356.26 1753.12,356.26 1728,381.37
  text "VIN65Vmax" at 2365.5,1424.5 h36
  text "VOUT" at 351.43,1367 h36
  text "VOUT" at 351.43,1006.5 h36
  text "GND" at 2484.5,888.09 h36
  text "INJ" at 351.43,726.5 h36
  text "EN" at 1890,634 h36
  text "GND" at 844.5,630.5 h36
  text "1" at 1424.05,588.5 h30
  text "2" at 1525.29,587.5 h30
  text "3" at 1630.5,588.5 h30
  text "<JUMPER SETTING>" at 1152.73,507 h30
  text "GND" at 351.43,449 h36
  text "JP1:" at 1114,444.5 h30
  text "1&2 -> EN LOW" at 1253,439.5 h30
  text "2&3 -> EN HIGH" at 1246.14,379.5 h30
  text "BSR256-" at 1780.5,255 h36
  text "VEMI" at 2460.5,243 h36
Top Solder:
  rectangle: 1467.7,1453.5 1505.2,1558.5
  rectangle: 1240.5,1469 1278,1558
Bottom Solder:
  rectangle: 2061.5,872.24 2189.5,946.29
  rectangle: 2061,973.74 2189.5,1057.24
M1 Board Outline:
  the board outline again, w10
M2 Board Dimensions:
  rectangle: 125,-400 500,-275
  rectangle: 0,-275 125,-150
  lines w7: 0,-275 1000,-275 ; 125,-400 125,-150 ; 250,-400 250,-150 ; 500,-400 500,-150 ; 750,-400 750,-150 ; 0,-400 0,-150 1000,-150 1000,-400 0,-400
M5 Assembly Top:
  lines w10: -292,-930.17 6308,-930.17 ; -292,-726.83 6310,-726.83 ; -292,-523.5 -292,-1133.5 3713,-1133.5 6310,-1133.5 6310,-523.5 -291.5,-523.5 -291.5,-1133.5 1284,-1133.5 ; 2173,-1133.5 2173,-523.5 ; 3440,-726.83 3440,-523.5 ; 4280,-726.83 4280,-523.5 ; 4902,-1140 4902,-937.17
  text "COMPONENTS MARKED 'DNP' SHOULD NOT BE POPULATED." at 1153.5,-318.5 h60
  text "ASSEMBLY VARIANT:" at 1153,-434 h60
  text ".VariantName" at 2189,-434 h60
  text "PCB VIEWED FROM TOP SIDE" at -228.5,-655.67 h60
  text "BOARD #:" at 2248,-655.67 h60
  text ".PRJ_Number" at 2793.5,-655.67 h60
  text "REV:" at 3638,-655.67 h60
  text ".PCB_Rev" at 3929.5,-655.67 h60
  text "SVN REV:" at 4476,-655.67 h60
  text ".VersionControl_RevNumber" at 4982,-655.67 h60
  text "TID #:" at 2248,-859 h60
  text ".TID" at 2793.5,-859 h60
  text "PLOT NAME =" at -228.5,-1064.34 h60
  text ".plot_File_Name" at 577,-1064.34 h60
  text "GENERATED    :" at 2250,-1064.34 h60
  text ".Print_Date" at 3119.5,-1064.34 h60
  text ".Print_Time" at 3848.5,-1064.34 h60
  text "TEXAS INSTRUMENTS" at 5113,-1064.34 h60
M6 Assembly Bottom:
  lines w10: -292.5,-727.33 6309.5,-727.33 ; -290.5,-930.67 6309.5,-930.67 ; 1115.5,-1140.5 1115.5,-937.67 ; 1737.5,-727.33 1737.5,-524 ; 2577.5,-727.33 2577.5,-524 ; 3844.5,-1134 3844.5,-524 ; 4733.5,-1134 6309,-1134 6309,-524 -292.5,-524 -292.5,-1134 2304.5,-1134 6309.5,-1134 6309.5,-524
  text "COMPONENTS MARKED 'DNP' SHOULD NOT BE POPULATED." at 6102,-318 h60
  text ".VariantName" at 5058,-434 h60
  text "ASSEMBLY VARIANT:" at 6097,-434 h60
  text ".VersionControl_RevNumber" at 1035.5,-656.17 h60
  text "SVN REV:" at 1541.5,-656.17 h60
  text ".PCB_Rev" at 2088,-656.17 h60
  text "REV:" at 2379.5,-656.17 h60
  text ".PRJ_Number" at 3224,-656.17 h60
  text "BOARD #:" at 3769.5,-656.17 h60
  text "PCB VIEWED FROM BOTTOM SIDE" at 6246,-656.17 h60
  text ".TID" at 3224,-859.5 h60
  text "TID #:" at 3769.5,-859.5 h60
  text "TEXAS INSTRUMENTS" at 904.5,-1064.84 h60
  text ".Print_Time" at 2169,-1064.84 h60
  text ".Print_Date" at 2898,-1064.84 h60
  text "GENERATED    :" at 3767.5,-1064.84 h60
  text ".plot_File_Name" at 5440.5,-1064.84 h60
  text "PLOT NAME =" at 6246,-1064.84 h60
M9 Title Sheet:
  drawing of 57 lines, arcs and shapes, not listed
  text "1" at 739.84,8036.5 h70
  text "2" at 3235.5,8036.5 h70
  text "3" at 5724.84,8036.5 h70
  text "4" at 8231.51,8036.5 h70
  text "5" at 10730.5,8036.5 h70
  text "6" at 13235.5,8036.5 h70
  text "A" at -416.5,6893.5 h70
  text "A" at 14383.5,6893.5 h70
  text "B" at -416.5,4513.5 h70
  text "B" at 14383.5,4513.5 h70
  text "C" at -416.5,2138.5 h70
  text "C" at 14383.5,2138.5 h70
  text "PROJECT TITLE:" at 11343.5,277.5 h45
  text ".PRJ_Title" at 11393.5,144.17 h70
  text "DESIGNED FOR:" at 11343.5,-23.5 h45
  text ".PRJ_Customer" at 11393.5,-163.5 h70
  text "D" at -416.5,-231.5 h70
  text "D" at 14383.5,-231.5 h70
  text "FILE NAME:" at 11343.5,-323.5 h45
  text ".PCB_File_Name_No_Path" at 11393.5,-443.5 h70
  text "Texas Instruments (TI) and/or its licensors do not warrant the accuracy or completeness of this specification" at 6374,-605.34 h45
  text "ENGINEER:" at 11343.5,-613.5 h45
  text "LAYOUT BY:" at 12848.5,-613.5 h45
  text "or any information contained therein. TI and/or its licensors do not warrant that this design will meet" at 6329.01,-718 h45
  text ".PRJ_Engineer" at 11393.5,-768.49 h70
  text ".PCB_Layout" at 12899,-768.49 h70
  text "the specifications, will be suitable for your application or fit for any particular purpose, or will operate in" at 6329.01,-830.67 h45
  text "ALTIUM DESIGNER VERSION:" at 12848.5,-923.5 h45
  text "an implementation. TI and/or its licensors do not warrant that the design is production worthy. You should" at 6329.01,-943.33 h45
  text "completely validate and test your design implementation to confirm the system functionality for your application." at 6374,-1056 h45
  text ".print_Scale" at 11393.5,-1056.83 h70
  text ".Application_BuildNumber" at 12899,-1056.83 h70
  text "1" at 739.84,-1263.5 h70
  text "2" at 3235.5,-1263.5 h70
  text "3" at 5724.84,-1263.5 h70
  text "4" at 8231.51,-1263.5 h70
  text "5" at 10730.5,-1263.5 h70
  text "6" at 13235.5,-1263.5 h70
M10 Fab Notes:
  drawing of 173 lines, arcs and shapes, not listed
  text "DESIGN INFORMATION" at 12378.02,6201 h60
  text "MIN. TRACK WIDTH:" at 11733.46,6021 h60
  text "8" at 12829.7,6021 h60
  text "MIL" at 12984.46,6021 h60
  text "MIN. CLEARANCE:" at 11733.46,5889 h60
  text "0.2" at 12769.7,5889 h60
  text "mm" at 12984.46,5889 h60
  text "MIN. VIA PAD SIZE:" at 11733.46,5757 h60
  text "24" at 12799.71,5757 h60
  text "MIL" at 12984.46,5757 h60
  text "0.05mm (2MIL)" at 12428.46,5615.29 h60
  text "MINIMUM ANNULAR RING" at 11404.23,5611 h60
  text "EXTERNAL" at 13136.46,5611 h60
  text "PER" at 11604.23,5493 h60
  text "IPC-D-275 CLASS 2 LEVEL C" at 11824.23,5493 h60
  text "MIL, HOLES" at 13312.46,5380.71 h60
  text "+/-" at 12920,5380 h60
  text "+/-" at 13774,5380 h60
  text "REGISTRATION TOLERANCES:" at 11404.23,5375 h60
  text "METAL" at 12604,5375 h60
  text "5" at 13180.2,5375 h60
  text "3" at 14013.2,5375 h60
  text "MIL" at 14129.46,5375 h60
  text "+/-" at 13774,5262 h60
  text "HOLE SIZE TOLERANCE (UNLESS OTHERWISE SPECIFIED):" at 11404.23,5257 h60
  text "3" at 14013.2,5257 h60
  text "MIL" at 14129.46,5257 h60
  text "MATERIAL:" at 11329.46,5047.54 h60
  text "FR-4 High Tg" at 12315.9,4907.21 h60
  text "FR-408" at 11750.46,4898.64 h60
  text "OTHER" at 13238.46,4898.64 h60
  text "X" at 12161,4895 h60
  text "62 MIL (1.6mm) +/-10%" at 12070.56,4735.92 h60
  text "THICKNESS:" at 11404.23,4731.64 h60
  text "X" at 11942.4,4731.64 h60
  text "OTHER" at 13355.46,4731.64 h60
  text "TOLERANCE:" at 11404.23,4573.64 h60
  text "X" at 12243.53,4573.64 h60
  text "ANSI IPC-6012 TYPE 3 CLASS 2" at 12430.48,4573.64 h60
  text "OTHER +/-" at 12430.46,4417.64 h60
  text "BOW & TWIST:" at 11404.23,4260.64 h60
  text "X" at 12243.53,4260.64 h60
  text "ANSI IPC-6012 TYPE 3 CLASS 2" at 12430.48,4260.64 h60
  text "OTHER +/-" at 12430.46,4102.13 h60
  text "DRILLING:" at 11329.46,3963.64 h60
  text "REFERENCE:" at 11404.23,3846.64 h60
  text "X" at 12052.46,3846.64 h60
  text "AS SHOWN" at 12239.46,3846.64 h60
  text "X" at 12953.46,3846.64 h60
  text "NC_DRILL FILES" at 13090.46,3846.64 h60
  text "PTH COPPER THICKNESS:" at 11404.23,3688.64 h60
  text "X" at 12534.46,3688.64 h60
  text "20-30 um" at 12671.46,3688.64 h60
  text "OTHER" at 13388.46,3688.64 h60
  text "BOARD FINISH:" at 11329.46,3529.64 h60
  text "SILKSCREEN:" at 11484.68,3411.64 h60
  text "X" at 12433.46,3411.64 h60
  text "TOP" at 12559.46,3411.64 h60
  text "X" at 12943.46,3411.64 h60
  text "BOTTOM" at 13070.46,3411.64 h60
  text "SILKSCREEN COLOR:" at 11484.68,3244.64 h60
  text "X" at 12432.42,3244.64 h60
  text "WHITE" at 12559.46,3244.64 h60
  text "OTHER" at 13070.46,3244.64 h60
  text "X" at 12563.42,3085.44 h60
  text "GREEN" at 12690.46,3085.44 h60
  text "OTHER" at 13308.46,3085.44 h60
  text "SOLDER RESIST COLOR:" at 11484.68,3074.64 h60
  text "X" at 12563.42,2915.44 h60
  text "MATTE" at 12690.46,2915.44 h60
  text "SEMI-GLOSS" at 13308,2914.8 h60
  text "IMMERSION GOLD (ENIG)" at 12390.46,2726.92 h60
  text "ENEPIG" at 13728,2723.64 h60
  text "SURFACE FINISH:" at 11329.46,2722.64 h60
  text "X" at 12203.51,2722.64 h60
  text "IMM. TIN/SILVER OR EQUIV" at 11659,2565.64 h60
  text "OTHER" at 13090.46,2565.64 h60
  text "ARRAY/PANEL:" at 11329.46,2386.64 h60
  text "CUT AND TRIM PER M1 BOARD OUTLINE" at 12390.46,2382.35 h60
  text "N.C. ROUTE" at 12390.46,2230.64 h60
  text "X" at 13069.46,2230.64 h60
  text "V. SCORE" at 13256.46,2230.64 h60
  text "CERTIFICATION:" at 11329.46,2093.64 h60
  text "MATERIALS AND WORKMANSHIP FOR ALL PCBS" at 12054.46,2093.64 h60
  text "TO MEET OR EXCEED THE REQUIREMENTS OF:" at 12054.46,1995.64 h60
  text "X" at 11680.96,1859.13 h60
  text "ANSI IPC-A-600F CLASS ->" at 11819.96,1859.13 h60
  text "X" at 13459.02,1859.13 h60
  text "2" at 13577.96,1859.14 h60
  text "1" at 13262.96,1857.64 h60
  text "3" at 13931.96,1857.64 h60
  text "X" at 12495.02,1699.64 h60
  text "RoHS" at 12631.96,1699.64 h60
  text "OTHER" at 13276.36,1699.64 h60
  text "PER ORDER" at 13673.42,1699.64 h60
  text "ALL BOARDS MUST MEET OR EXCEED UL94-V0 REQUIREMENTS." at 11357,1534 h60
  text "PCB MUST BEAR THE UL94V-0 UL REGISTERED MATERIAL ID NUMBER" at 11357,1414 h60
  text "ADDITIONAL REQUIREMENTS:" at 11329.46,1240.64 h60
  text "MICROSECTION:" at 11404.23,1125.64 h60
  text "YES" at 12309.96,1125.64 h60
  text "REQUIRED" at 13171.46,969.49 h60
  text "BARE BOARD ELEC. TEST:" at 11404.23,966.64 h60
  text "NONE" at 12709.96,966.64 h60
  text "X" at 13044.46,966.64 h60
  text "PER ORDER" at 13763.46,966.64 h60
M11 Gerber Information:
  lines w10: -292,-930.17 6308,-930.17 ; -292,-726.83 6310,-726.83 ; -292,-523.5 -292,-1133.5 3713,-1133.5 6310,-1133.5 6310,-523.5 -291.5,-523.5 -291.5,-1133.5 1284,-1133.5 ; 2173,-1133.5 2173,-523.5 ; 3440,-726.83 3440,-523.5 ; 4280,-726.83 4280,-523.5 ; 4902,-1140 4902,-937.17
  text "ALL ARTWORK VIEWED FROM TOP SIDE" at -228.5,-655.67 h60
  text "BOARD #:" at 2248,-655.67 h60
  text ".PRJ_Number" at 2793.5,-655.67 h60
  text "REV:" at 3638,-655.67 h60
  text ".PCB_Rev" at 3929.5,-655.67 h60
  text "SVN REV:" at 4476,-655.67 h60
  text ".VersionControl_RevNumber" at 4982,-655.67 h60
  text "LAYER NAME =" at -228.5,-858.49 h60
  text "TID #:" at 2248,-859 h60
  text ".TID" at 2793.5,-859 h60
  text "PLOT NAME =" at -228.5,-1064.34 h60
  text ".plot_File_Name" at 577,-1064.34 h60
  text "GENERATED    :" at 2250,-1064.34 h60
  text ".Print_Date" at 3119.5,-1064.34 h60
  text ".Print_Time" at 3848.5,-1064.34 h60
  text "TEXAS INSTRUMENTS" at 5113,-1064.34 h60
M12 Stackup:
  drawing of 269 lines, arcs and shapes, not listed
  text "Layer" at 2707.55,6065 h60
  text "Name" at 3117.47,6065 h60
  text "Material" at 4057.21,6065 h60
  text "Thickness" at 4916.97,6065 h60
  text "Constant" at 5566.81,6065 h60
  text "Board Layer Stack" at 6136.67,6065 h60
  text "1" at 2707.55,5945 h60
  text "Top Overlay" at 3117.47,5945 h60
  text "2" at 2707.55,5825 h60
  text "Top Solder" at 3117.47,5825 h60
  text "Solder Resist" at 4057.21,5825 h60
  text "0.40mil" at 4916.97,5825 h60
  text "3.5" at 5566.81,5825 h60
  text "3" at 2707.55,5705 h60
  text "Top Layer" at 3117.47,5705 h60
  text "Copper" at 4057.21,5705 h60
  text "2.80mil" at 4916.97,5705 h60
  text "4" at 2707.55,5585 h60
  text "Dielectric1" at 3117.47,5585 h60
  text "FR-4 High Tg" at 4057.21,5585 h60
  text "10.00mil" at 4916.97,5585 h60
  text "4.8" at 5566.81,5585 h60
  text "5" at 2707.55,5465 h60
  text "Signal Layer 1" at 3117.47,5465 h60
  text "Copper" at 4057.21,5465 h60
  text "1.42mil" at 4916.97,5465 h60
  text "6" at 2707.55,5345 h60
  text "Dielectric 2" at 3117.47,5345 h60
  text "FR-4 High Tg" at 4057.21,5345 h60
  text "32.00mil" at 4916.97,5345 h60
  text "4.2" at 5566.81,5345 h60
  text "7" at 2707.55,5225 h60
  text "Signal Layer 2" at 3117.47,5225 h60
  text "Copper" at 4057.21,5225 h60
  text "1.42mil" at 4916.97,5225 h60
  text "8" at 2707.55,5105 h60
  text "Dielectric 3" at 3117.47,5105 h60
  text "FR-4 High Tg" at 4057.21,5105 h60
  text "10.00mil" at 4916.97,5105 h60
  text "4.2" at 5566.81,5105 h60
  text "9" at 2707.55,4985 h60
  text "Bottom Layer" at 3117.47,4985 h60
  text "Copper" at 4057.21,4985 h60
  text "2.80mil" at 4916.97,4985 h60
  text "10" at 2707.55,4865 h60
  text "Bottom Solder" at 3117.47,4865 h60
  text "Solder Resist" at 4057.21,4865 h60
  text "0.40mil" at 4916.97,4865 h60
  text "3.5" at 5566.81,4865 h60
Drill Drawing:
  circle w10: c2734.99,4464.15 r27.63
  lines w10: 2707.36,4312.2 2762.62,4312.2 2762.62,4367.45 2707.36,4367.45 2707.36,4312.2 ; 2707.36,4616.09 2762.62,4616.09 2734.99,4560.84 2707.36,4616.09 ; 2707.36,4698.97 2721.18,4698.97 2734.99,4685.16 2748.8,4698.97 2762.62,4698.97 2748.8,4712.79 2762.62,4726.6 2748.8,4726.6 2734.99,4740.41 2721.18,4726.6 2707.36,4726.6 2721.18,4712.79 2707.36,4698.97
  lines w12: 2657.27,4274.9 9800.26,4274.9 ; 2657.27,4772.18 9800.26,4772.18 ; 2995.14,4150.58 2995.14,4896.5 ; 3327.14,4150.58 3327.14,4896.5 ; 3963.7,4150.58 3963.7,4896.5 ; 4222.84,4150.58 4222.84,4896.5 ; 4598,4150.58 4598,4896.5 ; 5322.33,4150.58 5322.33,4896.5 ; 5851.47,4150.58 5851.47,4896.5 ; 6154.76,4150.58 6154.76,4896.5 ; 6551.43,4150.58 6551.43,4896.5 ; 6990.27,4150.58 6990.27,4896.5 ; 7410.18,4150.58 7410.18,4896.5 ; 8037.02,4150.58 8037.02,4896.5 ; 8647.68,4150.58 8647.68,4896.5 ; 9085.44,4150.58 9085.44,4896.5 ; 2657.27,4150.58 9800.26,4150.58 9800.26,4896.5 2657.27,4896.5 2657.27,4150.58
  text "Symbol" at 2731.87,4809.48 h72
  text "Quantity" at 3032.43,4809.48 h72
  text "Finished Hole Size" at 3364.43,4809.48 h72
  text "Plated" at 4001,4809.48 h72
  text "Hole Type" at 4260.14,4809.48 h72
  text "Drill Layer Pair" at 4635.29,4809.48 h72
  text "Hole Tolerance" at 5359.63,4809.48 h72
  text "Via/Pad" at 5888.76,4809.48 h72
  text "Pad Shape" at 6192.06,4809.48 h72
  text "Template" at 6588.73,4809.48 h72
  text "Description" at 7027.57,4809.48 h72
  text "Hole Tolerance (+)" at 7447.48,4809.48 h72
  text "Hole Tolerance (-)" at 8074.32,4809.48 h72
  text "Hole Length" at 8684.97,4809.48 h72
  text "Routed Path Length" at 9122.74,4809.48 h72
  text "44" at 3032.43,4685.16 h60
  text "16.00mil (0.406mm)" at 3364.43,4685.16 h60
  text "PTH" at 4001,4685.16 h60
  text "Round" at 4260.14,4685.16 h60
  text "Top Layer - Bottom Layer" at 4635.29,4685.16 h60
  text "Via" at 5888.76,4685.16 h60
  text "Rounded" at 6192.06,4685.16 h60
  text "v81h41m0mx0" at 6588.73,4685.16 h60
  text "-" at 8684.97,4685.16 h60
  text "-" at 9122.74,4685.16 h60
  text "3" at 3032.43,4560.84 h60
  text "40.00mil (1.016mm)" at 3364.43,4560.84 h60
  text "PTH" at 4001,4560.84 h60
  text "Round" at 4260.14,4560.84 h60
  text "Top Layer - Bottom Layer" at 4635.29,4560.84 h60
  text "Pad" at 5888.76,4560.84 h60
  text "(Mixed)" at 6192.06,4560.84 h60
  text "(Mixed)" at 6588.73,4560.84 h60
  text "-" at 8684.97,4560.84 h60
  text "-" at 9122.74,4560.84 h60
  text "4" at 3032.43,4436.52 h60
  text "63.00mil (1.600mm)" at 3364.43,4436.52 h60
  text "PTH" at 4001,4436.52 h60
  text "Round" at 4260.14,4436.52 h60
  text "Top Layer - Bottom Layer" at 4635.29,4436.52 h60
  text "Pad" at 5888.76,4436.52 h60
  text "Rounded" at 6192.06,4436.52 h60
  text "c221h160" at 6588.73,4436.52 h60
  text "-" at 8684.97,4436.52 h60
  text "-" at 9122.74,4436.52 h60
  text "5" at 3032.43,4312.2 h60
  text "98.43mil (2.500mm)" at 3364.43,4312.2 h60
  text "PTH" at 4001,4312.2 h60
  text "Round" at 4260.14,4312.2 h60
  text "Top Layer - Bottom Layer" at 4635.29,4312.2 h60
  text "Pad" at 5888.76,4312.2 h60
  text "Rounded" at 6192.06,4312.2 h60
  text "c350h250" at 6588.73,4312.2 h60
  text "-" at 8684.97,4312.2 h60
  text "-" at 9122.74,4312.2 h60
  text "56 Total" at 3032.43,4187.88 h60
M17 Embedded Cavity:
  text ".Layer_Name" at 577,-858.49 h60
M18 Embedded Assembly:
  text ".Layer_Name" at 577,-858.49 h60
M19 Embedded Keepout:
  text ".Layer_Name" at 577,-858.49 h60

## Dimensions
0,0 to 0,1796.5 on M2 Board Dimensions
0,-400 to 1000,-400 on M2 Board Dimensions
